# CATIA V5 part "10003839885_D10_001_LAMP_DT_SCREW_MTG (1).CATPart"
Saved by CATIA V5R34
Part number: 10003839885_D10_001
Revision: V01
Definition: LAMP_DT_SCREW_MTG
Nomenclature: 327.300-03
Material "PC+ABS - Bayblend TX85F": density 1170 kg/m3, Young's modulus 2.2e+09 Pa, Poisson ratio 0.35
Material "PC+ABS - Bayblend TX85F": density 1170 kg/m3, Young's modulus 2.2e+09 Pa, Poisson ratio 0.35
Material "PMMA  - Plexiglas 8N": density 1190 kg/m3, Young's modulus 3.2e+09 Pa, Poisson ratio 0.35
Material "PMMA  - Plexiglas 8N": density 1190 kg/m3, Young's modulus 3.2e+09 Pa, Poisson ratio 0.35
Material "ABS - Acrylonitrile-Butadiene-Styrene": density 1040 kg/m3, Young's modulus 2.2e+09 Pa, Poisson ratio 0.35
Bounding box of the stored display mesh (mm): x -104.789 to 104.787, y -32.295 to 32.295, z -52 to 0.338
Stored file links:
  C:\Users\kumaan57\sc5\win\10003839885_D10_001_LAMP_DT_SCREW_MTG.CATPart
  C:\Users\kumaan57\sc5\win\10003666978_D10_001_HOUSING_WITH_SCREW_WIRE_HARNESS.CATPart
  C:\Users\kumaan57\sc5\win\10003666980_D10_001_HOUSING_WITH_SCREW_6_PIN_DT_CONNECTOR_.CATPart
  C:\Users\kumaan57\sc5\win\10003666975_D10_001_OUTER_LENS_WITH_SCREW.CATPart
  Part38.CATPart
  Part1.CATPart
  Part1_AllCATPart.CATPart
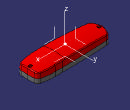
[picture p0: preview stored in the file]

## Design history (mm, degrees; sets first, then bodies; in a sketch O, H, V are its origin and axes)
AxisSystem1: origin (0, 0, 0), X (1, 0, 0), Y (0, 1, 0), Z (0, 0, 1)
Body1 (main body)
Body2 "LAMP"
  Solid1: solid without history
